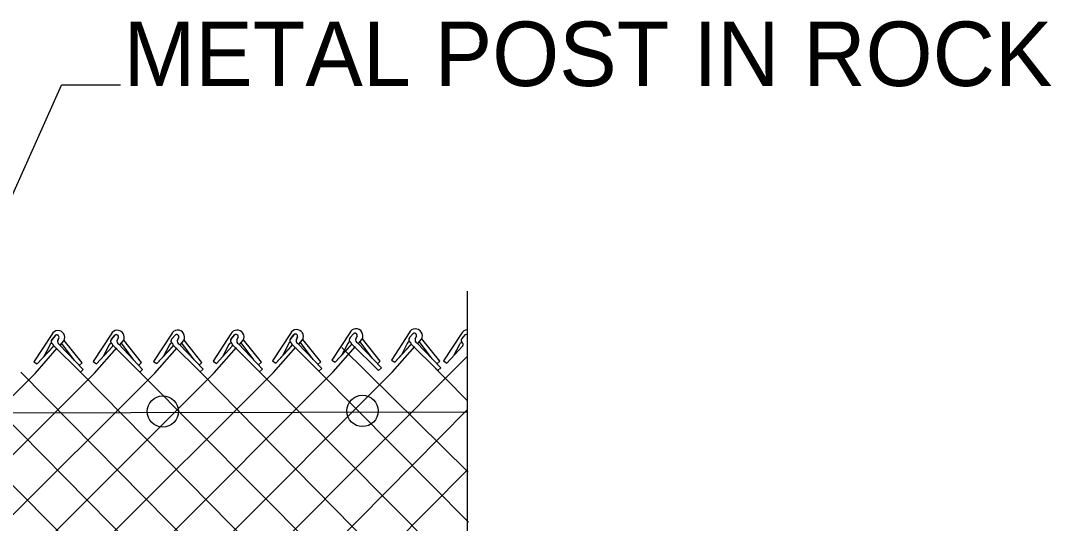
# Model space of a CAD drawing. Extents: x 0 to 2.85, y -0.1 to 1.83.
# Drawn here: x 1.173 to 1.3329, y 0.5382 to 0.6162 of the extents above; entities that cross this region are included whole.
import ezdxf

# ---------------------------------------------------------------- set-up
doc = ezdxf.new("R2010")
doc.units = 0
doc.layers.add('CT_Dimensions', color=7, linetype='Continuous')
doc.layers.add('sb_Chainlink Fence', color=7, linetype='Continuous')

msp = doc.modelspace()

# ---------------------------------------------------------------- linework, layer by layer
at = {"layer": 'CT_Dimensions'}
for p in [(1.1676591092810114, 0.580190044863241), (1.1884827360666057, 0.6061815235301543)]:
    msp.add_line(p, (1.1793396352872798, 0.6061815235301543), dxfattribs=at)
at = {"layer": 'sb_Chainlink Fence'}
for p, q in [((1.2422905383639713, 0.5165766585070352), (1.2423058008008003, 0.5742715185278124)), ((1.1777994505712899, 0.5675402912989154), (1.1750318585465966, 0.5633024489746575)), ((1.1778579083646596, 0.5667749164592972), (1.17836439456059, 0.5673809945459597)), ((1.1783175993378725, 0.567331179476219), (1.1778579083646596, 0.5667749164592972)), ((1.1789170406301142, 0.5670073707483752), (1.178731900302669, 0.5666007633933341)), ((1.1787325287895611, 0.566615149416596), (1.1789167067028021, 0.5669981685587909)), ((1.179132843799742, 0.5658759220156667), (1.1796963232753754, 0.5665500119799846)), ((1.1791403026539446, 0.5658861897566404), (1.1796991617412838, 0.5665523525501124)), ((1.1796963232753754, 0.5665500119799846), (1.1797376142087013, 0.5666281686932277)), ((1.1797376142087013, 0.5666281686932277), (1.1797727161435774, 0.5667117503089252)), ((1.18253134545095, 0.5631399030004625), (1.179750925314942, 0.5665999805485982)), ((1.18701909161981, 0.5675815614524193), (1.184251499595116, 0.5633437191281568)), ((1.187077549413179, 0.5668161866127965), (1.1875840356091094, 0.5674222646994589)), ((1.1875372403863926, 0.5673724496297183), (1.187077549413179, 0.5668161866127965)), ((1.1881366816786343, 0.5670486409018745), (1.1879515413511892, 0.566642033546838)), ((1.1879521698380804, 0.5666564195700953), (1.1881363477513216, 0.5670394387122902)), ((1.1883524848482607, 0.565917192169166), (1.1889159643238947, 0.5665912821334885)), ((1.1883599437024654, 0.5659274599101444), (1.1889188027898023, 0.5665936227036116)), ((1.1889159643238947, 0.5665912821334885), (1.18895725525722, 0.566669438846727)), ((1.18895725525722, 0.566669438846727), (1.1889923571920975, 0.5667530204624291)), ((1.1917509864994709, 0.5631811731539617), (1.1889705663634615, 0.5666412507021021)), ((1.19638459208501, 0.5675973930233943), (1.1936170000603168, 0.5633595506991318)), ((1.196443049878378, 0.5668320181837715), (1.19694953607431, 0.5674380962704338)), ((1.1969027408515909, 0.5673882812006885), (1.196443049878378, 0.5668320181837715)), ((1.197502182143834, 0.5670644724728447), (1.1973170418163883, 0.5666578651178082)), ((1.1973176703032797, 0.5666722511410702), (1.1975018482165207, 0.5670552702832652)), ((1.1977179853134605, 0.565933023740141), (1.1982814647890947, 0.5666071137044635)), ((1.197725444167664, 0.5659432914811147), (1.198284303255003, 0.5666094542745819)), ((1.1982814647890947, 0.5666071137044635), (1.1983227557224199, 0.566685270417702)), ((1.1983227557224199, 0.566685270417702), (1.198357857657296, 0.5667688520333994)), ((1.20111648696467, 0.5631970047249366), (1.1983360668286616, 0.5666570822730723)), ((1.2056050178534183, 0.5676218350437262), (1.2028374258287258, 0.5633839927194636)), ((1.2056634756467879, 0.5668564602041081), (1.206169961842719, 0.5674625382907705)), ((1.20612316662, 0.5674127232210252), (1.2056634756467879, 0.5668564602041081)), ((1.206722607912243, 0.5670889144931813), (1.2065374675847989, 0.5666823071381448)), ((1.20653809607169, 0.5666966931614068), (1.206722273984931, 0.5670797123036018)), ((1.206938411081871, 0.5659574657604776), (1.2075018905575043, 0.5666315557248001)), ((1.2069458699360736, 0.5659677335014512), (1.207504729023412, 0.5666338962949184)), ((1.2075018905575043, 0.5666315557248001), (1.2075431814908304, 0.5667097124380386)), ((1.2075431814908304, 0.5667097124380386), (1.2075782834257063, 0.566793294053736)), ((1.2103369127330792, 0.5632214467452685), (1.2075564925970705, 0.5666815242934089)), ((1.2148261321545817, 0.5676886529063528), (1.2120585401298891, 0.5634508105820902)), ((1.2148845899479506, 0.5669232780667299), (1.215391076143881, 0.5675293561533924)), ((1.2153442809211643, 0.567479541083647), (1.2148845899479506, 0.5669232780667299)), ((1.215943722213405, 0.5671557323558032), (1.2157585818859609, 0.5667491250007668)), ((1.215759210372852, 0.5667635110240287), (1.2159433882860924, 0.5671465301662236)), ((1.2161595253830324, 0.5660242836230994), (1.2167230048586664, 0.5666983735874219)), ((1.2161669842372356, 0.5660345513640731), (1.216725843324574, 0.5667007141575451)), ((1.2183665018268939, 0.5636622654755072), (1.2164098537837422, 0.5662968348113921)), ((1.2167230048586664, 0.5666983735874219), (1.2167642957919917, 0.5667765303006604)), ((1.2167642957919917, 0.5667765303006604), (1.2167993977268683, 0.5668601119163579)), ((1.2195580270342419, 0.5632882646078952), (1.2167776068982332, 0.5667483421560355)), ((1.224056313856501, 0.5678047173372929), (1.2212887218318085, 0.5635668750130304)), ((1.22411477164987, 0.5670393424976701), (1.2246212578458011, 0.5676454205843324)), ((1.2245744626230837, 0.5675956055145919), (1.22411477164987, 0.5670393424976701)), ((1.2251739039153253, 0.567271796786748), (1.2249887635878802, 0.5668651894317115)), ((1.2249893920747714, 0.5668795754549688), (1.2251735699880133, 0.5672625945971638)), ((1.2252344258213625, 0.5662489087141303), (1.2289475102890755, 0.5623449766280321)), ((1.2253897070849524, 0.5661403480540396), (1.2259531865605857, 0.5668144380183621)), ((1.2253971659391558, 0.5661506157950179), (1.2259560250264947, 0.5668167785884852)), ((1.2275966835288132, 0.5637783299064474), (1.2256400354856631, 0.5664128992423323)), ((1.2259531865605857, 0.5668144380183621), (1.2259944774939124, 0.5668925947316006)), ((1.2259944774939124, 0.5668925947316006), (1.2260295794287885, 0.5669761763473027)), ((1.2287882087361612, 0.5634043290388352), (1.2260077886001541, 0.5668644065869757)), ((1.2332806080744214, 0.5678012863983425), (1.2305130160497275, 0.5635634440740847)), ((1.2333390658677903, 0.5670359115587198), (1.2338455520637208, 0.5676419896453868)), ((1.233798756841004, 0.5675921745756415), (1.2333390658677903, 0.5670359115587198)), ((1.2343981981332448, 0.5672683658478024), (1.2342130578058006, 0.5668617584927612)), ((1.2342136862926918, 0.5668761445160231), (1.2343978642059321, 0.567259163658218)), ((1.2344587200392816, 0.5662454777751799), (1.2381718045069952, 0.5623415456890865)), ((1.2346140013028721, 0.5661369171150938), (1.235177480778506, 0.5668110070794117)), ((1.2346214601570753, 0.5661471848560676), (1.2351803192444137, 0.5668133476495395)), ((1.2368209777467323, 0.5637748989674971), (1.2348643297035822, 0.5664094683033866)), ((1.235177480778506, 0.5668110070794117), (1.2352187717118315, 0.5668891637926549)), ((1.2352187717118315, 0.5668891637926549), (1.235253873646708, 0.5669727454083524)), ((1.2380125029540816, 0.5634008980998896), (1.235232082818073, 0.5668609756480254)), ((1.2413994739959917, 0.56766656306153), (1.2386099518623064, 0.563443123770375)), ((1.241916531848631, 0.5674547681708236), (1.2414539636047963, 0.5669008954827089)), ((1.1752062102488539, 0.5614856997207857), (1.1786610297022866, 0.5654165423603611)), ((1.1755442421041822, 0.5629562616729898), (1.1780145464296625, 0.565645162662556)), ((1.1755442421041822, 0.5629562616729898), (1.1779988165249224, 0.5656293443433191)), ((1.1774905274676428, 0.5658722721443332), (1.1765704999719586, 0.5640911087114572)), ((1.178065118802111, 0.5658165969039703), (1.1822396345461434, 0.5616675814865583)), ((1.1789775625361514, 0.5659844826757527), (1.1826906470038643, 0.5620805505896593)), ((1.1813398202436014, 0.5635139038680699), (1.179383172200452, 0.5661484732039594)), ((1.1844258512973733, 0.561526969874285), (1.187880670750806, 0.5654578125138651)), ((1.1847638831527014, 0.5629975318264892), (1.1872341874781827, 0.5656864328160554)), ((1.1847638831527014, 0.5629975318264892), (1.1872184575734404, 0.5656706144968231)), ((1.1867101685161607, 0.5659135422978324), (1.1857901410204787, 0.5641323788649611)), ((1.187284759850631, 0.5658578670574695), (1.1914592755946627, 0.5617088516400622)), ((1.1881972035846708, 0.5660257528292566), (1.1919102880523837, 0.5621218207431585)), ((1.1905594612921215, 0.5635551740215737), (1.1886028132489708, 0.5661897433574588)), ((1.1937913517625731, 0.5615428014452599), (1.1972461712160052, 0.5654736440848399)), ((1.1941293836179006, 0.5630133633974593), (1.1965996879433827, 0.5657022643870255)), ((1.1941293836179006, 0.5630133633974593), (1.196583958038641, 0.5656864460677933)), ((1.1960756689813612, 0.5659293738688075), (1.1951556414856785, 0.5641482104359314)), ((1.1966502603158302, 0.5658736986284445), (1.200824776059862, 0.5617246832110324)), ((1.19756270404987, 0.5660415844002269), (1.2012757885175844, 0.5621376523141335)), ((1.1999249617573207, 0.5635710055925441), (1.1979683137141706, 0.5662055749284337)), ((1.2030117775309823, 0.5615672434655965), (1.2064665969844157, 0.5654980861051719)), ((1.203349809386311, 0.5630378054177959), (1.2058201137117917, 0.5657267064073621)), ((1.203349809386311, 0.5630378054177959), (1.205804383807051, 0.56571088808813)), ((1.2052960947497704, 0.5659538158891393), (1.2043760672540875, 0.564172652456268)), ((1.20587068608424, 0.5658981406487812), (1.2100452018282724, 0.5617491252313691)), ((1.2067831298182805, 0.5660660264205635), (1.2104962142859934, 0.5621620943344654)), ((1.2091453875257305, 0.5635954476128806), (1.207188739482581, 0.5662300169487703)), ((1.212232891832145, 0.5616340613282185), (1.2156877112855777, 0.5655649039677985)), ((1.212570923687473, 0.5631046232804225), (1.2150412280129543, 0.565793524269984)), ((1.212570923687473, 0.5631046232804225), (1.215025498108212, 0.5657777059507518)), ((1.2145172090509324, 0.5660206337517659), (1.2135971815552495, 0.5642394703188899)), ((1.2150918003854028, 0.565964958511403), (1.2192663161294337, 0.561815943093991)), ((1.2160042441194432, 0.5661328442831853), (1.219717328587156, 0.562228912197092)), ((1.2214630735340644, 0.5617501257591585), (1.2249178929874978, 0.5656809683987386)), ((1.2218011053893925, 0.5632206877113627), (1.2242714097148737, 0.5659095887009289)), ((1.2218011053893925, 0.5632206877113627), (1.224255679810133, 0.5658937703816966)), ((1.222823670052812, 0.5655347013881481), (1.2424007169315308, 0.5461516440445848)), ((1.223747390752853, 0.5661366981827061), (1.2228273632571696, 0.5643555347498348)), ((1.2243219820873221, 0.5660810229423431), (1.2284964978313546, 0.5619320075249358)), ((1.2306873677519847, 0.5617466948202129), (1.2341421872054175, 0.5656775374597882)), ((1.2310253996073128, 0.563217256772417), (1.233495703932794, 0.5659061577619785)), ((1.2310253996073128, 0.563217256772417), (1.2334799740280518, 0.5658903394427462)), ((1.2329716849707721, 0.5661332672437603), (1.2320516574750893, 0.5643521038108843)), ((1.2335462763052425, 0.5660775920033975), (1.237720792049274, 0.5619285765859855)), ((1.2391205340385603, 0.5630942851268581), (1.2416047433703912, 0.5657703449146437)), ((1.2391205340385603, 0.5630942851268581), (1.241588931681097, 0.5657546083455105)), ((1.2410819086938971, 0.5660001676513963), (1.2401526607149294, 0.564223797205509)), ((1.1170663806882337, 0.4387057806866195), (1.2423146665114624, 0.5641446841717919)), ((1.1750318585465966, 0.5633024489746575), (1.1755442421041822, 0.5629562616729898)), ((1.18253134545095, 0.5631399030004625), (1.1820803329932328, 0.562726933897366)), ((1.184251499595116, 0.5633437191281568), (1.1847638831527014, 0.5629975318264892)), ((1.1917509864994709, 0.5631811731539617), (1.1912999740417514, 0.5627682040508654)), ((1.1936170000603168, 0.5633595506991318), (1.1941293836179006, 0.5630133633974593)), ((1.20111648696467, 0.5631970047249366), (1.2006654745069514, 0.5627840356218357)), ((1.2028374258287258, 0.5633839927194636), (1.203349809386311, 0.5630378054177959)), ((1.2103369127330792, 0.5632214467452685), (1.209885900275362, 0.5628084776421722)), ((1.2120585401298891, 0.5634508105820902), (1.212570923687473, 0.5631046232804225)), ((1.2195580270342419, 0.5632882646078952), (1.219107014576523, 0.5628752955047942)), ((1.2212887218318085, 0.5635668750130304), (1.2218011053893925, 0.5632206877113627)), ((1.2287882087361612, 0.5634043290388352), (1.228337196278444, 0.5629913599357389)), ((1.2305130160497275, 0.5635634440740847), (1.2310253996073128, 0.563217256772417)), ((1.235633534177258, 0.5640030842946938), (1.2422006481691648, 0.5573316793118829)), ((1.2380125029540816, 0.5634008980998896), (1.2375614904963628, 0.5629879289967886)), ((1.2386099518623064, 0.563443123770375), (1.2391205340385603, 0.5630942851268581)), ((1.0856272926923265, 0.47212115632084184), (1.1752062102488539, 0.5614856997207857)), ((1.0856296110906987, 0.4444539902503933), (1.2030117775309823, 0.5615672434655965)), ((1.086031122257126, 0.45411934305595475), (1.1937913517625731, 0.5615428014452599)), ((1.0861919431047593, 0.46351323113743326), (1.1844258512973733, 0.561526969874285)), ((1.0889412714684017, 0.43860628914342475), (1.212232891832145, 0.5616340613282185)), ((1.098624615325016, 0.4387014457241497), (1.2214630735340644, 0.5617501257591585)), ((1.1078450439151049, 0.4387247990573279), (1.2306873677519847, 0.5617466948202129)), ((1.1545640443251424, 0.561488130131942), (1.242202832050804, 0.4729775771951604)), ((1.1637851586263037, 0.5615549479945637), (1.2423944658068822, 0.4820903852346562)), ((1.1730153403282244, 0.5616710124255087), (1.2421925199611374, 0.49170328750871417)), ((1.1826906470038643, 0.5620805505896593), (1.1822396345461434, 0.5616675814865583)), ((1.1822396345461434, 0.5616675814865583), (1.2421467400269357, 0.5009699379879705)), ((1.1919102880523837, 0.5621218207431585), (1.1914592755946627, 0.5617088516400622)), ((1.1914592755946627, 0.5617088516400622), (1.2405411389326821, 0.5123525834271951)), ((1.2012757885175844, 0.5621376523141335), (1.200824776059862, 0.5617246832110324)), ((1.200824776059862, 0.5617246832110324), (1.2424112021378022, 0.5194915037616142)), ((1.2104962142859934, 0.5621620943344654), (1.2100452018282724, 0.5617491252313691)), ((1.2100452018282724, 0.5617491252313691), (1.2422192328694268, 0.5293245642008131)), ((1.219717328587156, 0.562228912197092), (1.2192663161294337, 0.561815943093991)), ((1.2192663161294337, 0.561815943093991), (1.2424966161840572, 0.5384349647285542)), ((1.2289475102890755, 0.5623449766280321), (1.2284964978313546, 0.5619320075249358)), ((1.2381718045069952, 0.5623415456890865), (1.237720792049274, 0.5619285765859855)), ((1.2387748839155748, 0.5616254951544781), (1.2387748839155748, 0.5616254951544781)), ((1.1262970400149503, 0.4386375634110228), (1.2423211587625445, 0.5558689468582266)), ((1.135521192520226, 0.4386888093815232), (1.242193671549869, 0.5464454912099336))]:
    msp.add_line(p, q, dxfattribs=at)
msp.add_lwpolyline([(1.2421880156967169, 0.5554824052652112), (1.085878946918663, 0.5551669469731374)], dxfattribs=at)
for centre in [(1.1950301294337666, 0.5555841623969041), (1.2260178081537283, 0.5556698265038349)]:
    msp.add_circle(centre, 0.0024276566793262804, dxfattribs=at)
for centre, radius, start, end in [((1.1787618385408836, 0.5670704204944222), 0.0010709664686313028, 331.07013048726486, 153.97678331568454), ((1.187981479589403, 0.5671116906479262), 0.0010709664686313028, 331.07013048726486, 153.97678331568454), ((1.1973469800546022, 0.5671275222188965), 0.0010709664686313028, 331.07013048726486, 153.97678331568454), ((1.2065674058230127, 0.5671519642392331), 0.0010709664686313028, 331.07013048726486, 153.97678331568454), ((1.2157885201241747, 0.567218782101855), 0.0010709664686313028, 331.07013048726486, 153.97678331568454), ((1.2250187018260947, 0.5673348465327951), 0.0010709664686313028, 331.07013048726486, 153.97678331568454), ((1.2342429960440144, 0.5673314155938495), 0.0010709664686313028, 331.07013048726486, 153.97678331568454), ((1.2423618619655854, 0.5671966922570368), 0.0010709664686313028, 92.67062549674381, 153.97678331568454), ((1.17815664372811, 0.5664521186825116), 0.00044009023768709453, 140.4986600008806, 233.30225261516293), ((1.1781686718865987, 0.5664527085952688), 0.0004476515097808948, 133.96418530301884, 232.53135776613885), ((1.1785852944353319, 0.5671099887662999), 0.0003472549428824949, 342.81175570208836, 140.43380871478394), ((1.178586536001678, 0.5671116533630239), 0.0003491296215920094, 341.0313574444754, 129.51439849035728), ((1.1791767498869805, 0.5664206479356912), 0.00047949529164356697, 156.78028482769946, 245.4548333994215), ((1.1873762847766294, 0.5664933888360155), 0.00044009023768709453, 140.4986600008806, 233.30225261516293), ((1.1873883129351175, 0.566493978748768), 0.0004476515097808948, 133.96418530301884, 232.53135776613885), ((1.1878049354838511, 0.5671512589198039), 0.0003472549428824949, 342.81175570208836, 140.43380871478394), ((1.187806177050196, 0.5671529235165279), 0.0003491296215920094, 341.0313574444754, 129.51439849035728), ((1.1883963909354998, 0.5664619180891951), 0.00047949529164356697, 156.78028482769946, 245.4548333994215), ((1.1967417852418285, 0.5665092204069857), 0.00044009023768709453, 140.4986600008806, 233.30225261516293), ((1.1967538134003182, 0.566509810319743), 0.0004476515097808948, 133.96418530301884, 232.53135776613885), ((1.1971704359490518, 0.5671670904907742), 0.0003472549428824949, 342.81175570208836, 140.43380871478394), ((1.197171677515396, 0.5671687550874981), 0.0003491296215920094, 341.0313574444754, 129.51439849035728), ((1.1977618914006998, 0.5664777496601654), 0.00047949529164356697, 156.78028482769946, 245.4548333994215), ((1.205962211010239, 0.5665336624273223), 0.00044009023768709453, 140.4986600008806, 233.30225261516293), ((1.2059742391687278, 0.5665342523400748), 0.0004476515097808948, 133.96418530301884, 232.53135776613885), ((1.2063908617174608, 0.5671915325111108), 0.0003472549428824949, 342.81175570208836, 140.43380871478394), ((1.2063921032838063, 0.5671931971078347), 0.0003491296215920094, 341.0313574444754, 129.51439849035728), ((1.2069823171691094, 0.566502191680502), 0.00047949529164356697, 156.78028482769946, 245.4548333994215), ((1.2148059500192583, 0.5659716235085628), 0.0002928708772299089, 319.318461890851, 170.3665589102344), ((1.215183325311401, 0.5666004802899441), 0.00044009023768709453, 140.4986600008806, 233.30225261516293), ((1.2151953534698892, 0.5666010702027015), 0.0004476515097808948, 133.96418530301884, 232.53135776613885), ((1.2156119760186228, 0.5672583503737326), 0.0003472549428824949, 342.81175570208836, 140.43380871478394), ((1.2156132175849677, 0.5672600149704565), 0.0003491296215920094, 341.0313574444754, 129.51439849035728), ((1.2162034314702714, 0.566569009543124), 0.00047949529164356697, 156.78028482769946, 245.4548333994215), ((1.224036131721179, 0.5660876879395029), 0.0002928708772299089, 319.318461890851, 170.3665589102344), ((1.224413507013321, 0.5667165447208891), 0.00044009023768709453, 140.4986600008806, 233.30225261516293), ((1.2244255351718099, 0.5667171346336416), 0.0004476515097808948, 133.96418530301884, 232.53135776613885), ((1.2248421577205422, 0.5673744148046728), 0.0003472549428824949, 342.81175570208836, 140.43380871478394), ((1.2248433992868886, 0.5673760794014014), 0.0003491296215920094, 341.0313574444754, 129.51439849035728), ((1.2254336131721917, 0.5666850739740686), 0.00047949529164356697, 156.78028482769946, 245.4548333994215), ((1.233260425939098, 0.5660842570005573), 0.0002928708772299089, 319.318461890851, 170.3665589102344), ((1.2336378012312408, 0.5667131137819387), 0.00044009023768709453, 140.4986600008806, 233.30225261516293), ((1.233649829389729, 0.5667137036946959), 0.0004476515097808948, 133.96418530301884, 232.53135776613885), ((1.2340664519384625, 0.5673709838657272), 0.0003472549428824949, 342.81175570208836, 140.43380871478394), ((1.2340676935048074, 0.5673726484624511), 0.0003491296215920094, 341.0313574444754, 129.51439849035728), ((1.2346579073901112, 0.5666816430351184), 0.00047949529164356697, 156.78028482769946, 245.4548333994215), ((1.2413703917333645, 0.5659496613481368), 0.0002928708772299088, 319.02146199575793, 170.0695590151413), ((1.2417630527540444, 0.5665770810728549), 0.0004476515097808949, 133.66718540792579, 232.2343578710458), ((1.2421386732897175, 0.5671854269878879), 0.0003491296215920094, 62.642004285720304, 129.51439849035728), ((1.1777792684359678, 0.5658232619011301), 0.0002928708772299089, 319.318461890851, 170.3665589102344), ((1.1869989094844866, 0.5658645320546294), 0.0002928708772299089, 319.318461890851, 170.3665589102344), ((1.1963644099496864, 0.5658803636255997), 0.0002928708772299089, 319.318461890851, 170.3665589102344), ((1.205584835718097, 0.5659048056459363), 0.0002928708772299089, 319.318461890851, 170.3665589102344)]:
    msp.add_arc(centre, radius, start, end, dxfattribs=at)

# ---------------------------------------------------------------- texts
at = {"layer": 'CT_Dimensions'}
msp.add_text('METAL POST IN ROCK', height=0.01, dxfattribs=at).set_placement((1.1889308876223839, 0.6060659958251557))

doc.saveas('drawing.dxf')
